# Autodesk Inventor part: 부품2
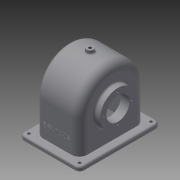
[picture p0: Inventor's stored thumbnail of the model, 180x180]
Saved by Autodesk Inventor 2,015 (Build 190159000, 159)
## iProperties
Created: 2016-01
Part Number: 부품2
Material: 일반
Document SubType Name: Modeling
Designer: Administrator
Density: 1 g/cm^3
Appearance: 기본값
Author: Administrator
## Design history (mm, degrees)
sketch "스케치1"
  geometry: L1 (-44, 70)-(44, 70); L2 (52, 62)-(52, -62); L3 (44, -70)-(-44, -70); L4 (-52, -62)-(-52, 62); L5 (-52, -70)-(52, 70); A1 r 8 centre (-44, 62) between (-44, 70) and (-52, 62); A2 r 8 centre (44, 62) between (52, 62) and (44, 70); A3 r 8 centre (44, -62) between (44, -70) and (52, -62); A4 r 8 centre (-44, -62) between (-52, -62) and (-44, -70); 2 further points
  constraints: 10 end point, 8 point on circle, 8 tangent, 4 centre point, 4 point on line, 3 equal radius, 2 parallel, 1 coincident, 1 horizontal, 1 midpoint, 1 perpendicular
  dimensions: "d0" = 104 distance between parallel lines of L4 L2; "d1" = 140 distance between parallel lines of L3 L1; "d2" = 8 radius of A1
extrude "돌출1" new body sketch "스케치1" distance "d3" = 7; taper "d4" = 0 deg
sketch "스케치2"
  geometry: A1 r 8 centre (-44, 62) between (-44, 70) and (-52, 62) reference; A2 r 8 centre (44, 62) between (52, 62) and (44, 70) reference; A3 r 8 centre (44, -62) between (44, -70) and (52, -62) reference; A4 r 8 centre (-44, -62) between (-52, -62) and (-44, -70) reference; 5 further points
  constraints: 4 coincident
hole "구멍1" sketch "스케치2" at (-44, 62), (44, 62), (44, -62), (-44, -62) diameter "d5" = 5; stored, may be unused: countersink angle "d9" = 90 deg, drill point angle "d11" = 118 deg; dims "d6" = 6, "d7" = 4, "d8" = 2, "d10" = 8
fillet "모깎기1" dims "d12" = 3
sketch "스케치3"
  geometry: L1 (62, 0)-(-62, 0) reference; L2 (-57, 64)-(57, 64); L3 (57, 64)-(57, 0); L4 (57, 0)-(-57, 0); L5 (-57, 0)-(-57, 64); C1 r 57 at (0, 64); 2 further points
  constraints: 8 end point, 3 midpoint, 2 parallel, 1 centre point, 1 horizontal, 1 perpendicular
  dimensions: "d13" = 114 distance of L2.start L2.end; "d14" = 64 distance of L4.end L2.start; "d15" = 114 diameter of C1
extrude "돌출2" join sketch "스케치3" stored distance "d16" = 77; taper "d17" = 0 deg
fillet "모깎기2" dims "d18" = 14
sketch "스케치4"
  geometry: L1 (62, 4)-(-62, 4) reference; L2 (62, 0)-(62, 4) reference; L3 (62, 0)-(-62, 0) reference; L4 (-62, 0)-(-62, 4) reference; L5 (-51, 64)-(51, 64); L6 (51, 64)-(51, 0); L7 (51, 0)-(-51, 0); L8 (-51, 0)-(-51, 64); C1 r 51 at (0, 64); 2 further points
  constraints: 8 end point, 3 midpoint, 2 parallel, 1 centre point, 1 horizontal, 1 perpendicular
  dimensions: "d19" = 64 distance of L7.end L5.start; "d20" = 102 distance of L5.start L5.end; "d21" = 102 diameter of C1
extrude "돌출3" cut sketch "스케치4" stored distance "d22" = 67; taper "d23" = 0 deg
fillet "모깎기3" dims "d24" = 9
sketch "스케치5"
  geometry: L1 (-24.5, 0)-(24.5, 0) reference; L2 (47.571, 60)-(-52.714, 60); L3 (38.5, 7)-(38.5, 64) reference; L4 (38.5, 107)-(38.5, 64) reference; L5 (33.5, 64)-(33.5, 106) reference; L6 (33.5, 64)-(33.5, 0) reference; L7 (19.5, 60)-(19.5, 88); L8 (19.5, 88)-(33.5, 99.747); L9 (35.5, 60)-(35.5, 94.899); L10 (35.5, 94.899)-(38.5, 97.416); L11 (38.5, 97.416)-(33.5, 99.747); L12 (-33.5, 106)-(-33.5, 64) reference; L13 (-38.5, 64)-(-38.5, 107) reference; L14 (-33.5, 0)-(-33.5, 64) reference; L15 (-33.5, 60)-(-48.5, 60); L16 (-48.5, 60)-(-48.5, 91); L17 (-48.5, 91)-(-33.5, 91); L18 (-33.5, 91)-(-33.5, 60); 1 further point
  constraints: 20 end point, 6 point on line, 3 parallel, 2 horizontal, 2 vertical, 1 perpendicular
  dimensions: "d25" = 60 distance between parallel lines of L1 L2; "d26" = 56 diameter of L7.end L2; "d27" = 50 deg angle of L7 L8; "d28" = 3 distance between parallel lines of L4 L9; "d29" = 16 distance between parallel lines of L7 L9; "d30" = 5 distance between parallel lines of L10 L8; "d31" = 62 diameter of L17 L2; "d32" = 10 distance between parallel lines of L16 L13
revolve "회전1" sketch "스케치5" stored, may be unused: angle "d33" = 90 deg
sketch "스케치6"
  geometry: L1 (38.5, 107)-(38.5, 64) reference; L2 (38.5, 7)-(38.5, 64) reference; L3 (-24.5, 0)-(24.5, 0) reference; L4 (-48.5, 29)-(-48.5, 91) reference; L5 (55.682, 60)-(-66.24, 60); L6 (19.5, 88)-(33.5, 99.747) reference; L7 (38.5, 97.416)-(35.5, 94.899); L8 (35.5, 94.899)-(35.5, 80); L9 (35.5, 80)-(-48.5, 80); L10 (38.5, 97.416)-(38.5, 60); L11 (-48.5, 80)-(-48.5, 60); 1 further point
  constraints: 12 end point, 5 point on line, 2 perpendicular, 1 horizontal, 1 midpoint, 1 parallel
  dimensions: "d34" = 60 distance between parallel lines of L3 L5; "d35" = 5 distance between parallel lines of L6 L7; "d36" = 3 distance between parallel lines of L1 L8; "d37" = 40 diameter of L9 L5
revolve "회전2" sketch "스케치6" stored, may be unused: angle "d38" = 90 deg
sketch "스케치7"
  geometry: C1 r 20 at (0, 0) reference; C2 r 31 at (0, 0) reference; A1 r 24 centre (0, 0) between (-24, 0) and (24, 0); 3 further points
  constraints: 4 point on circle, 1 centre point, 1 coincident
  dimensions: "d39" = 48 diameter of A1
hole "구멍2" sketch "스케치7" at (-24, 0), (24, 0), (0, 24), (0, -24) diameter "d40" = 3; stored, may be unused: countersink angle "d44" = 90 deg, drill point angle "d46" = 118 deg; dims "d41" = 6, "d42" = 4, "d43" = 2, "d45" = 8
sketch "스케치8"
  geometry: C1 r 20 at (0, 0) reference; C2 r 34.899 at (0, 0) reference; A1 r 28 centre (0, 0) between (28, 0) and (0, 28); 3 further points
  constraints: 4 point on circle, 1 centre point, 1 coincident
  dimensions: "d48" = 56 diameter of A1
hole "구멍3" sketch "스케치8" at (28, 0), (0, 28), (-28, 0), (0, -28) diameter "d49" = 3; stored, may be unused: countersink angle "d53" = 90 deg, drill point angle "d55" = 118 deg; dims "d50" = 6, "d51" = 4, "d52" = 2, "d54" = 9
sketch "스케치11"
  geometry: L1 (33.5, 64)-(33.5, 106) reference; L2 (24.5, 115)-(-24.5, 115) reference; L3 (24.5, 121)-(-24.5, 121) reference; L4 (0, 115)-(0, 146.184); L5 (0, 117.899)-(6, 117.899); L6 (6, 117.899)-(6, 127); L7 (6, 127)-(0, 127); 1 further point
  constraints: 8 end point, 3 perpendicular, 2 point on line, 1 midpoint, 1 vertical
  dimensions: "d67" = 6 distance between parallel lines of L3 L7; "d68" = 12 diameter of L6 L4
revolve "회전4" sketch "스케치11" stored, may be unused: angle "d69" = 90 deg
sketch "스케치12"
  geometry: 2 further points
  constraints: 1 coincident
hole "구멍5" sketch "스케치12" at (0, 0) diameter "d70" = 5; stored, may be unused: countersink angle "d74" = 90 deg, drill point angle "d76" = 118 deg; dims "d71" = 6, "d72" = 4, "d73" = 2, "d75" = 9
fillet "모깎기5" dims "d77" = 3
feature "스레드1" dims "d79" = 6, "d80" = 0
feature "스레드2" dims "d81" = 6, "d82" = 0
feature "스레드3" dims "d83" = 6, "d84" = 0
feature "스레드4" dims "d85" = 6, "d86" = 0
feature "스레드5" dims "d87" = 7, "d88" = 0
feature "스레드6" dims "d89" = 7, "d90" = 0
feature "스레드7" dims "d91" = 7, "d92" = 0
feature "스레드8" dims "d93" = 7, "d94" = 0
sketch "스케치13"
  geometry: L1 (0.403, -29)-(48.597, -29); L2 (48.597, -29)-(48.597, -39); L3 (48.597, -39)-(0.403, -39); L4 (0.403, -39)-(0.403, -29); 1 further point
  constraints: 2 other
sketch "스케치14"
  geometry: 1 further point
feature "엠보싱1" dims "d0" = 104, "d1" = 140, "d2" = 8, "d98" = 0.5, "d99" = 0
feature "스레드9" dims "d100" = 12, "d101" = 0.5
node "솔리드1"
node "투영된 루프1"
node "투영된 루프2"
node "투영된 루프3"
